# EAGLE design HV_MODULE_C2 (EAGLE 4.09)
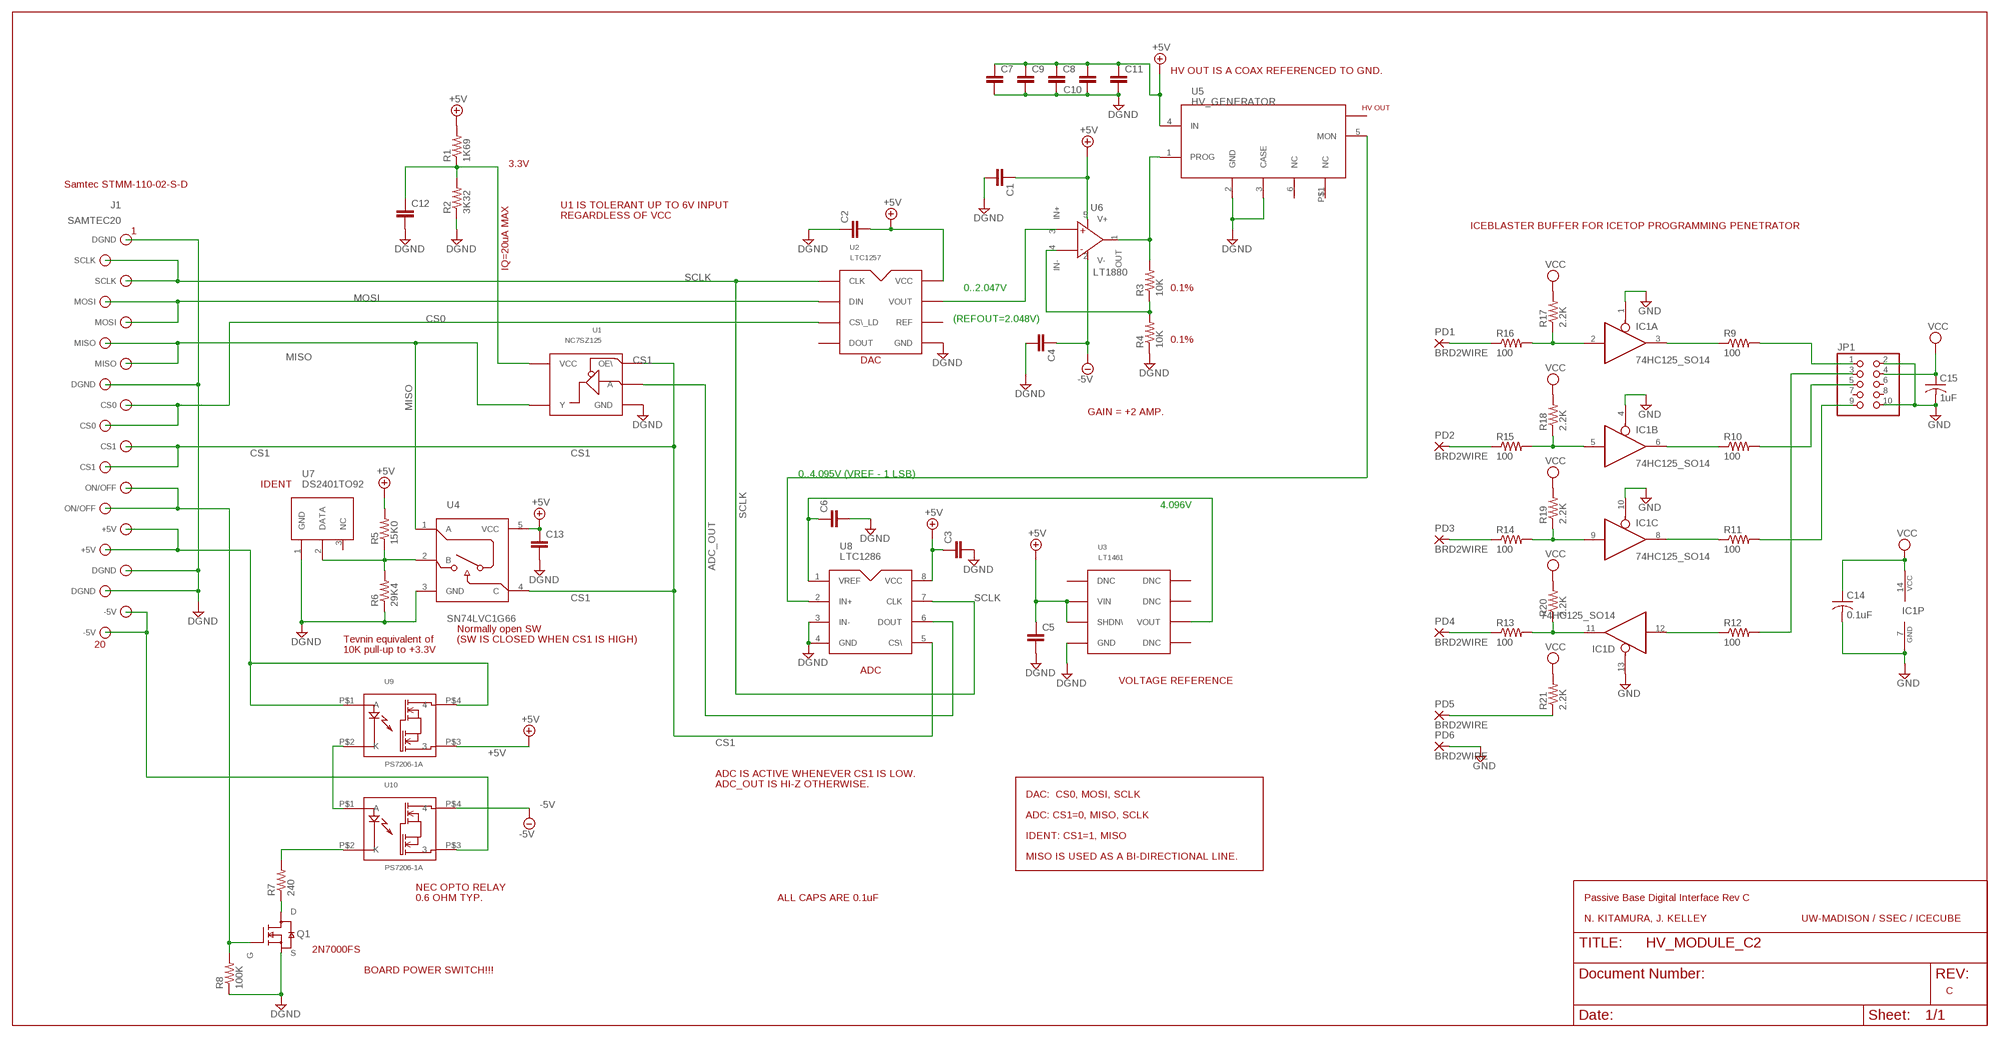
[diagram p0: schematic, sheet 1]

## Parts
C1  C-EUC0805  [C0805@1]
C2  C-EUC0805  [C0805@1]
C3  C-EUC0805  [C0805@1]
C4  C-EUC0805  [C0805@1]
C5  C-EUC0805  [C0805@1]
C6  C-EUC0805  [C0805@1]
C7  C-EUC0805  [C0805@1]
C8  C-EUC0805  [C0805@1]
C9  C-EUC0805  [C0805@1]
C10  C-EUC0805  [C0805@1]
C11  C-EUC0805  [C0805@1]
C12  C-EUC0805  [C0805@1]
C13  C-EUC0805  [C0805@1]
C14  0.1uF  C-USC0805  [C0805]
C15  1uF  C-USC0805  [C0805]
IC1  74HC125_SO14  [SO14]
J1  SAMTEC20  [SAMTEC20]
JP1  PINHD-2X5  [2X05]
PD1  BRD2WIRE  [BRD2WIRE]
PD2  BRD2WIRE  [BRD2WIRE]
PD3  BRD2WIRE  [BRD2WIRE]
PD4  BRD2WIRE  [BRD2WIRE]
PD5  BRD2WIRE  [BRD2WIRE]
PD6  BRD2WIRE  [BRD2WIRE]
Q1  2N7000FS  [TO92]
R1  1K69  R-US_M0805  [M0805]
R2  3K32  R-US_M0805  [M0805]
R3  10K  R-US_R0805  [R0805]
R4  10K  R-US_R0805  [R0805]
R5  15K0  R-US_M0805  [M0805]
R6  29K4  R-US_M0805  [M0805]
R7  240  R-US_M0805  [M0805]
R8  100K  R-US_M0805  [M0805]
R9  100  R-US_R0805  [R0805]
R10  100  R-US_R0805  [R0805]
R11  100  R-US_R0805  [R0805]
R12  100  R-US_R0805  [R0805]
R13  100  R-US_R0805  [R0805]
R14  100  R-US_R0805  [R0805]
R15  100  R-US_R0805  [R0805]
R16  100  R-US_R0805  [R0805]
R17  2.2K  R-US_R0805  [R0805]
R18  2.2K  R-US_R0805  [R0805]
R19  2.2K  R-US_R0805  [R0805]
R20  2.2K  R-US_R0805  [R0805]
R21  2.2K  R-US_R0805  [R0805]
U1  NC7SZ125  [SOT23-5]
U2  LTC1257  LTC1451  [SO8]
U3  LT1461  [SO8]
U4  SN74LVC1G66  [SOT23-5]
U5  HV_GENERATOR  EMCO1  [EMCO1]
U6  LT1880  [SOT23-5]
U7  DS2401TO92  [TO92]
U8  LTC1286  [SO8]
U9  PS7206-1A  [PS7206]
U10  PS7206-1A  [PS7206]

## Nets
3.3V: C12.1 R1.1 R2.2 U1.5(VCC)
+5V: C1.1 C2.2 C3.1 C5.1 C7.1 C8.1 C9.1 C10.2 C11.1 C13.1 R1.2 R5.2 U2.8(VCC) U3.2(VIN) U3.3(SHDN\) U4.5(VCC) U5.4(IN) U6.5(V+) U8.8(VCC) U9.P$3
-5V: C4.1 U6.2(V-) U10.P$4
ADC_OUT: U1.2(A) U8.6(DOUT)
BOARD_ONOFF: J1.P$13(ON/OFF) J1.P$14(ON/OFF) Q1.2(G) R8.2
CS0: J1.P$9(CS0) J1.P$10(CS0) U2.3(CS\_LD)
CS1: J1.P$11(CS1) J1.P$12(CS1) U1.1(OE\) U4.4(C) U8.5(CS\)
DGND: C1.2 C2.1 C3.2 C4.2 C5.2 C6.2 C7.2 C8.2 C9.2 C10.1 C11.2 C12.2 C13.2 J1.P$1(DGND) J1.P$8(DGND) J1.P$17(DGND) J1.P$18(DGND) Q1.1(S) R2.1 R4.1 R6.1 R8.1 U1.3(GND) U2.5(GND) U3.4(GND) U4.3(GND) U5.2(GND) U5.3(CASE) U7.1(GND) U8.3(IN-) U8.4(GND)
GND: C14.2 C15.2 IC1.1(A:OE) IC1.4(B:OE) IC1.7(P:GND) IC1.10(C:OE) IC1.13(D:OE) JP1.2 JP1.10 PD6.2(P)
HV_MON: U5.5(MON) U8.2(IN+)
HV_PROG: R3.2 U5.1(PROG) U6.1(OUT)
MISO: J1.P$6(MISO) J1.P$7(MISO) U1.4(Y) U4.1(A)
MOSI: J1.P$4(MOSI) J1.P$5(MOSI) U2.2(DIN)
N$1: U9.P$2(K) U10.P$1(A)
N$2: R5.1 R6.2 U4.2(B) U7.2(DATA)
N$3: IC1.2(A:I) R16.2 R17.1
N$4: Q1.3(D) R7.1
N$5: R7.2 U10.P$2(K)
N$6: IC1.9(C:I) R14.2 R19.1
N$7: IC1.11(D:O) R13.2 R20.1
N$8: IC1.12(D:I) R12.1
N$9: IC1.8(C:O) R11.1
N$10: R3.1 R4.2 U6.4(IN-)
N$11: IC1.6(B:O) R10.1
N$12: J1.P$15(+5V) J1.P$16(+5V) U9.P$1(A) U9.P$4
N$13: IC1.3(A:O) R9.1
N$14: IC1.5(B:I) R15.2 R18.1
N$15: J1.P$19(-5V) J1.P$20(-5V) U10.P$3
N$16: PD5.2(P) R21.1
N$24: U2.7(VOUT) U6.3(IN+)
N$32: C6.1 U3.6(VOUT) U8.1(VREF)
SCLK: J1.P$2(SCLK) J1.P$3(SCLK) U2.1(CLK) U8.7(CLK)
TCK_IN: PD1.2(P) R16.1
TCK_OUT: JP1.1 R9.2
TDI_IN: PD3.2(P) R14.1
TDI_OUT: JP1.9 R11.2
TDO_IN: JP1.3 R12.2
TDO_OUT: PD4.2(P) R13.1
TMS_IN: PD2.2(P) R15.1
TMS_OUT: JP1.5 R10.2
VCC: C14.1 C15.1 IC1.14(P:VCC) JP1.4 R17.2 R18.2 R19.2 R20.2 R21.2
Unconnected: JP1.6 JP1.7 JP1.8 U2.4(DOUT) U2.6(REF) U3.1(DNC) U3.5(DNC) U3.7(DNC) U3.8(DNC) U5.6(NC) U5.P$1(NC) U7.3(NC)

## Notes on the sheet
- HV OUT IS A COAX REFERENCED TO GND.
- 3.3V
- Samtec STMM-110-02-S-D
- U1 IS TOLERANT UP TO 6V INPUT
- REGARDLESS OF VCC
- ICEBLASTER BUFFER FOR ICETOP PROGRAMMING PENETRATOR
- IQ=20uA MAX
- 0..2.047V | 0.1%
- (REFOUT=2.048V)
- 0.1%
- DAC
- GAIN = +2 AMP.
- 0..4.095V (VREF - 1 LSB)
- IDENT
- 4.096V
- Normally open SW
- Tevnin equivalent of | (SW IS CLOSED WHEN CS1 IS HIGH)
- 10K pull-up to +3.3V
- ADC
- VOLTAGE REFERENCE
- ADC IS ACTIVE WHENEVER CS1 IS LOW.
- ADC_OUT IS HI-Z OTHERWISE.
- DAC:  CS0, MOSI, SCLK
- ADC: CS1=0, MISO, SCLK
- IDENT: CS1=1, MISO
- MISO IS USED AS A BI-DIRECTIONAL LINE.
- NEC OPTO RELAY
- 0.6 OHM TYP. | ALL CAPS ARE 0.1uF | Passive Base Digital Interface Rev C
- N. KITAMURA, J. KELLEY | UW-MADISON / SSEC / ICECUBE
- 2N7000FS
- BOARD POWER SWITCH!!!
- C

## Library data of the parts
C1-C13 = rcl:C-EU: CAPACITOR, European symbol
C14 C15 = rcl:C-US: CAPACITOR, American symbol
IC1 = JK1:74HC125_SO14
J1 = EMCO:SAMTEC20
JP1 = pinhead:PINHD-2X5: PIN HEADER
PD1-PD6 = JK1:BRD2WIRE: Board to wire, 0.076"
Q1 = FBD_lib:2N7000FS
R1-R21 = rcl:R-US_: RESISTOR, American symbol
U1 = HVM:NC7SZ125
U2 = EMCO:LTC1451: LINEAR TECHYNOLOGY 12-BIT DAC VOUT(MAX) = 4.095V, REFOUT (INTERNAL) = 2.048V
U3 = EMCO:LT1461: VOLTAGE REFERENCE. SUFFIX SPECIFIES VOLTAGE OUT.
U4 = HVM:SN74LVC1G66: BILATERAL ANALOG SWITCH NORMALLY OPEN
U5 = HVM:EMCO1: EMCO 9730 HV GENERATOR
U6 = HVM:LT1880: RAIL-TO-RAIL PICOAMP INPUT CURRENT PRECISION OPAMP
U7 = HVM:DS2401: DALLAS SILICON SERIAL NUMBER DEVICE
U8 = EMCO:LTC1286: 12-BIT ADC DIFF INPUT
U9 U10 = HVM:PS7206-1A

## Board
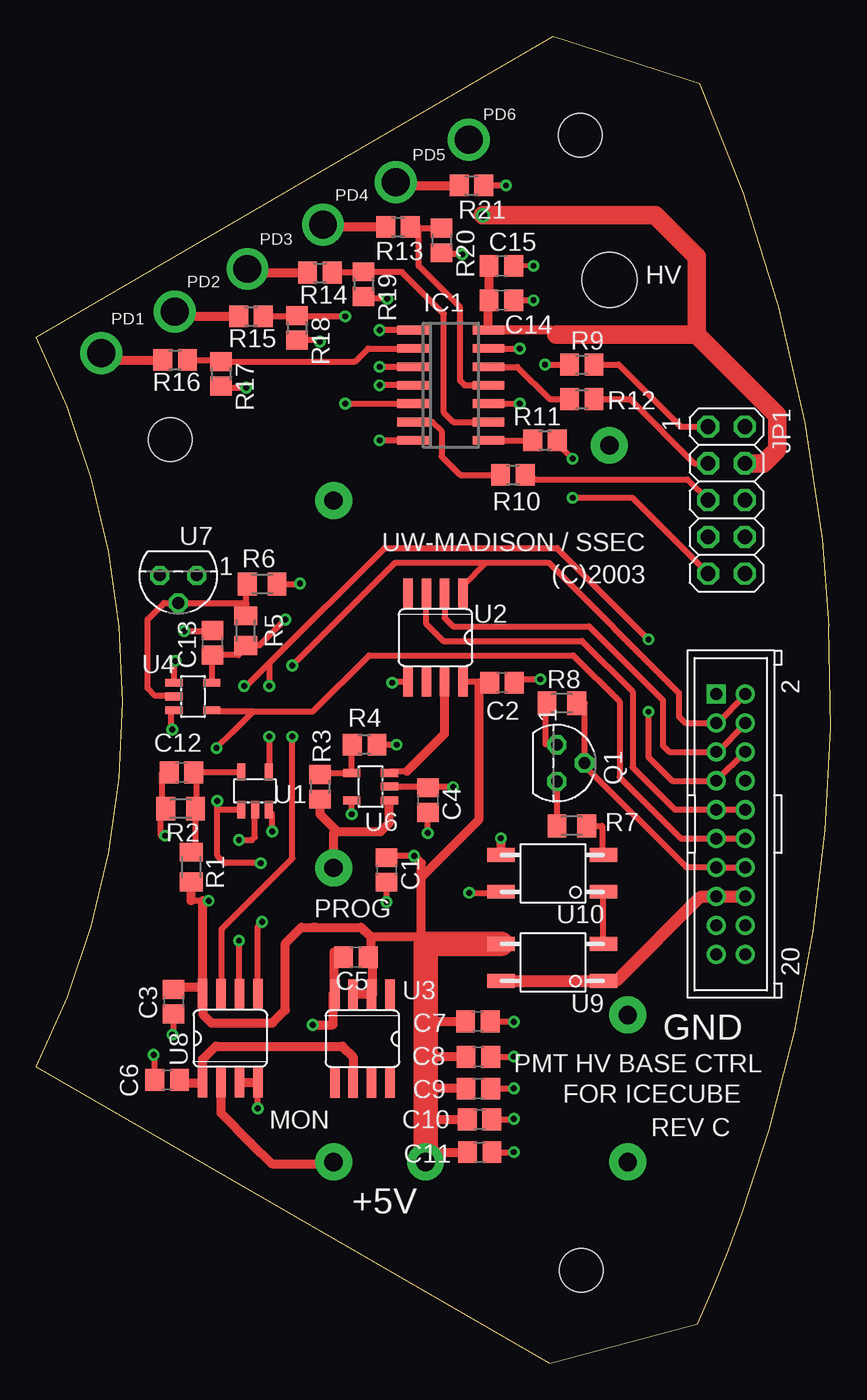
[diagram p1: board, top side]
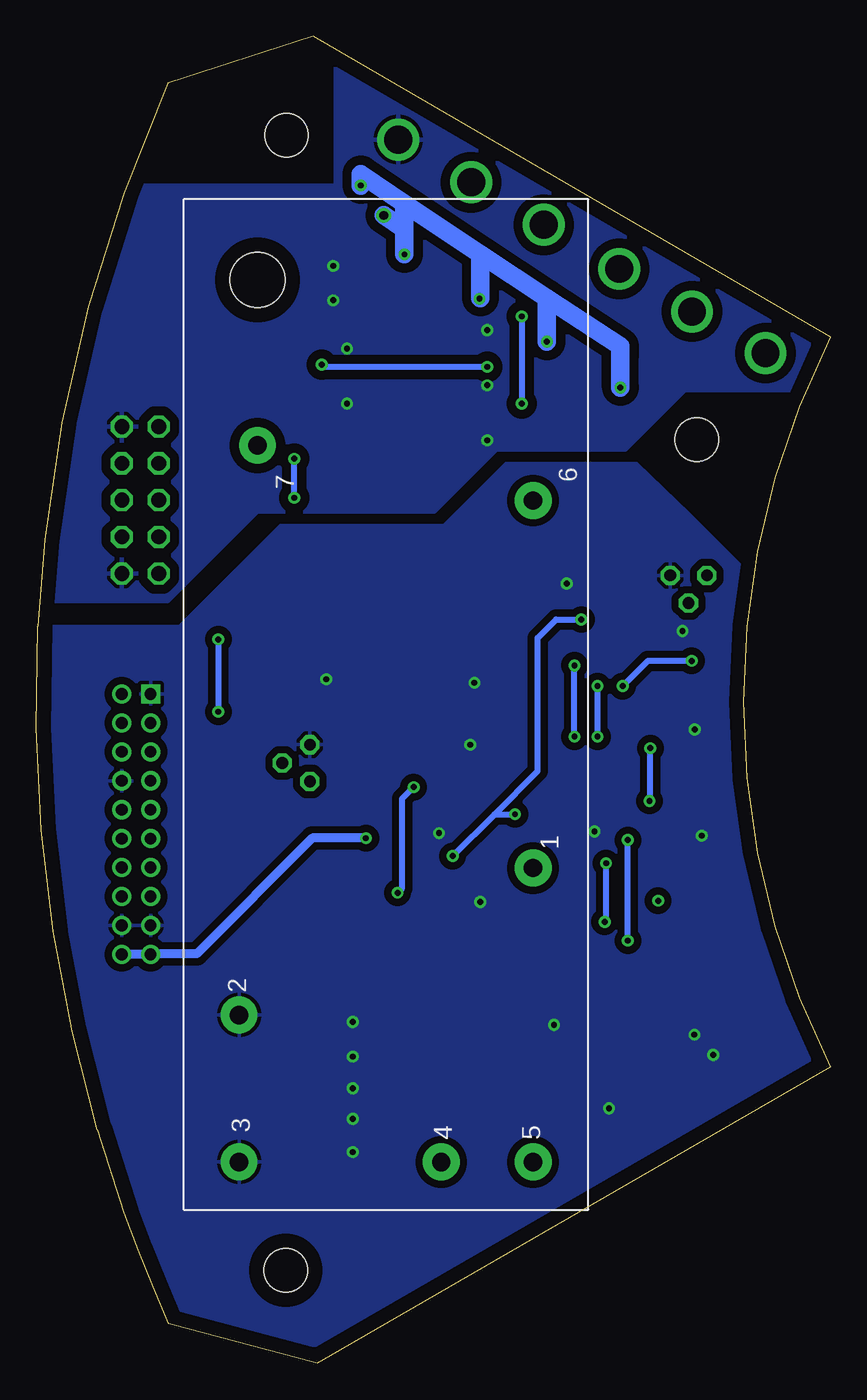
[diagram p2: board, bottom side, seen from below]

Size 54.9 x 91.74 mm. Coordinates in mm from the lower left corner, seen from the top.
Outline: 45.72,2.75 35.47,0 0,20.48 arc53 0,70.93 35.75,91.75 45.81,88.48 arc-18 54.31,56.93 54.78,50.95 arc-19 50.66,16.12
Outline: 45.72,2.75 arc5 48.81,10.42 50.66,16.12
Copper layers used: Top, Bottom
Holes 3 mm at 37.6,84.9 9.25,63.84 37.66,6.43
Milling: 10 lines

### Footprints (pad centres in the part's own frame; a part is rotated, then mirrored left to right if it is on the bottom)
C0805 = smd 1.3 x 1.5: 1 -0.85,0; 2 0.85,0
SO14 = smd 0.6 x 2.2: 1 -3.81,-2.6; 2 -2.54,-2.6; 3 -1.27,-2.6; 4 0,-2.6; 5 1.27,-2.6; 6 2.54,-2.6; 7 3.81,-2.6; 8 3.81,2.6; 9 2.54,2.6; 10 1.27,2.6; 11 0,2.6; 12 -1.27,2.6; 13 -2.54,2.6; 14 -3.81,2.6
SAMTEC20 = drill 0.813 square: P$1 -9,-1 | drill 0.813 round: P$2 -9,1; P$3 -7,-1; P$4 -7,1; P$5 -5,-1; P$6 -5,1; P$7 -3,-1; P$8 -3,1; P$9 -1,-1; P$10 -1,1; P$11 1,-1; P$12 1,1; P$13 3,-1; P$14 3,1; P$15 5,-1; P$16 5,1; P$17 7,-1; P$18 7,1; P$19 9,-1; P$20 9,1
2X05 = drill 1.016 octagon: 1 -5.08,-1.27; 2 -5.08,1.27; 3 -2.54,-1.27; 4 -2.54,1.27; 5 0,-1.27; 6 0,1.27; 7 2.54,-1.27; 8 2.54,1.27; 9 5.08,-1.27; 10 5.08,1.27
BRD2WIRE = drill 1.93 pad 2.54 round: 2 0,0
TO92 = drill 0.813 octagon: 1 -1.27,0; 2 0,1.905; 3 1.27,0
M0805 = smd 1.3 x 1.6: 1 -1.029,0; 2 1.029,0
R0805 = smd 1.3 x 1.5: 1 -0.85,0; 2 0.85,0
SOT23-5 = smd 0.55 x 1.2: 1 -0.95,-1.3; 2 0,-1.3; 3 0.95,-1.3; 4 0.95,1.3; 5 -0.95,1.3
SO8 = smd 0.66 x 2.032: 1 -1.905,-3.073; 2 -0.635,-3.073; 3 0.635,-3.073; 4 1.905,-3.073; 5 1.905,3.073; 6 0.635,3.073; 7 -0.635,3.073; 8 -1.905,3.073
EMCO1 = drill 1.27 pad 2.54 round: 1 37.338,24.13; 2 47.498,3.81; 3 57.658,3.81; 4 57.658,17.78; 5 57.658,24.13; 6 11.938,24.13; P$1 8.128,5.08 | hole 3.81: -3.302,5.08
TO92' = drill 0.813 octagon: 1 0,0; 2 1.27,1.905; 3 2.54,0
PS7206 = smd 1.93 x 0.965: P$1 -3.54,1.27; P$2 -3.54,-1.27; P$3 3.54,-1.27; P$4 3.54,1.27

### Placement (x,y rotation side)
C1  [C0805]  24.22,34.11 270 top
C2  [C0805]  32.19,47.06 180 top
C3  [C0805]  9.49,25.01 270 top
C4  [C0805]  27.07,38.94 270 top
C5  [C0805]  22.09,28.08 180 top
C6  [C0805]  9.05,19.59 180 top
C7  [C0805]  30.52,23.64 0 top
C8  [C0805]  30.55,21.18 0 top
C9  [C0805]  30.55,18.99 0 top
C10  [C0805]  30.64,16.87 180 top
C11  [C0805]  30.65,14.59 0 top
C12  [C0805]  10.04,40.84 180 top
C13  [C0805]  12.18,49.81 90 top
C14  32.15,73.49 0 top
C15  32.15,75.87 0 top
IC1  28.65,67.61 270 top
J1  47.99,37.27 270 top
JP1  47.7,59.67 270 top
PD1  4.5,69.83 0 top
PD2  9.58,72.72 0 top
PD3  14.6,75.66 0 top
PD4  19.82,78.7 0 top
PD5  24.84,81.64 0 top
PD6  29.88,84.6 0 top
Q1  35.98,41.49 270 top
R1  10.72,34.31 270 top
R2  9.98,38.34 0 top
R3  19.62,39.85 270 top
R4  22.7,42.77 180 top
R5  14.49,50.65 270 top
R6  15.62,53.88 180 top
R7  37.02,37.15 0 top
R8  36.32,45.63 0 top
R9  37.7,69.04 0 top
R10  32.94,61.42 0 top
R11  35.16,63.8 0 top
R12  37.7,66.66 0 top
R13  25,78.57 0 top
R14  19.6,75.39 0 top
R15  14.84,72.37 0 top
R16  9.6,69.36 0 top
R17  12.78,68.41 270 top
R18  18.02,71.58 270 top
R19  22.62,74.6 270 top
R20  28.02,77.61 270 top
R21  30.08,81.42 0 top
U1  15.12,39.58 0 top
U2  27.59,50.18 180 top
U3  22.54,22.43 180 top
U4  10.84,46.1 270 top
U5  44.69,71.58 270 bottom
U6  23.11,39.87 90 top
U7  DS2401TO92  [TO92']  11.09,54.47 180 top
U8  13.41,22.47 0 top
U9  35.66,27.71 180 top
U10  35.66,33.87 180 top

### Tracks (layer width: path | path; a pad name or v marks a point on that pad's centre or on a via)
3.3V
  Top 0.406: 11.01,40.84 11.01,40.78 | 11.01,40.84 C12.1 11.11,40.84 11.11,38.34 R2.2 11.01,35.34 R1.1 | U1.5 11.01,40.88 11.01,40.84
+5V  (via drill 0.41)
  Top 0.254: 26.93,28.98 26.71,28.98 26.71,29 | C13.1 12.18,49 12.14,49.04 12.13,49.03 | 14.52,49.51 14.49,49.55 R5.2
  Top 0.305: 22.91,28.1 C5.1 | 23.21,28.38 23.19,28.38 23.11,28.3 | 26.91,21.18 26.91,22.04 26.91,22.05
  Top 0.406: v21.81,37.96 U6.5 | C2.2 31.32,47.06 31.31,47.05 31.26,47.1 U2.8 | 26.91,19 26.92,18.99 26.91,18.99 26.91,16.87 | 26.93,21.18 26.91,21.18 | 26.91,21.18 C8.1 | 26.91,21.18 26.91,23.64 | 27.01,21.18 27.01,19 29.61,19 29.61,18.99 C9.1 | 11.51,31.98 10.71,31.98 | 24.22,34.92 24.21,34.91 | 24.22,34.92 C1.1 | v26.11,35.07 24.37,35.07 24.22,34.92 | 12.13,49.03 U4.5 | C13.1 13.97,48.96 14.52,49.51 | R5.2 15.43,49.62 v17.22,51.42
  Top 0.61: 23.21,25.51 23.21,25.4 | 23.21,25.51 U3.2 U3.3 | 23.21,28.38 23.21,25.51 | U3.3 | U3.3 21.91,25.6 | U2.8 29.5,47.43 | 22.91,28.1 23.11,28.3 23.11,29.5 | 26.61,33.6 30.61,37.6 30.61,47.05 31.31,47.05 | 26.61,33.6 26.61,29 26.71,29 26.81,29.1 26.41,29.5 23.11,29.5 | C9.1 26.92,18.99 | 26.91,16.87 C10.2 | 26.91,23.64 C7.1 | C8.1 27.01,21.18 | R1.2 10.71,31.98 | 11.51,25.53 U8.8 | 11.51,26.02 11.51,25.53 | v11.91,31.98 11.51,31.98 11.51,26.02 | U8.8 11.51,25.53 | 11.51,26.02 U8.8 | 11.51,25.53 11.51,24.13 12.11,23.53 16.32,23.53 17.22,24.43 17.22,29.04 18.33,30.15 19.29,30.15 | 23.11,29.5 23.1,29.5 22.46,30.15 19.29,30.15 | 19.29,30.15 19.13,30.15 | 9.45,26.02 9.49,25.97 C3.1 | 9.45,26.02 11.51,26.02 | 9.45,26.02 9.44,26.02 | 26.61,33.6 26.61,34.57 v26.11,35.07 | U5.4 26.91,13.8 27.71,14.59 C11.1
  Top 1.676: U9.P$3 26.93,28.98 26.93,21.18 | 26.91,22.05 26.91,13.8
  Bottom 0.406: v21.81,37.96 23.22,37.96 23.26,37.93 | v26.11,35.07 23.26,37.93 | v17.22,51.42 18.97,51.42 20.24,50.15 20.24,40.94 23.26,37.93
-5V  (via drill 0.41)
  Top 0.254: 24.41,39.86 U6.2
  Top 0.406: 24.41,39.86 27.04,39.86 27.07,39.82 C4.1 27.07,39.83 v28.81,39.83 | U10.P$4 32.12,32.55 32.15,32.53 v29.92,32.53
  Bottom 0.406: v28.81,39.83 29.6,39.04 29.6,32.85 v29.92,32.53
ADC_OUT  (via drill 0.41)
  Top 0.254: 14.05,29.22 v14.01,29.22 | U1.2 15.12,38.29 U1.2
  Top 0.406: U8.6 14.05,29.22 | v14.01,36.18 14.91,36.18 15.11,36.38 U1.2
  Bottom 0.254: 14.02,29.22 14.05,29.19 | v14.01,29.22 14.02,29.22 | 14.02,29.22 14.01,29.23
  Bottom 0.406: 14.01,29.23 v14.01,36.18
BOARD_ONOFF
  Top 0.254: Q1.2 37.89,41.33 | 47.01,34.3 J1.P$13 | J1.P$14 49.01,34.3 | J1.P$14 | J1.P$14
  Top 0.406: 37.91,41.49 37.91,41.4 | Q1.2 37.91,41.49 | R8.2 37.91,45.63 37.91,41.49 | 37.89,41.33 44.91,34.3 47.01,34.3 | J1.P$13 J1.P$14
CS0
  Top 0.254: J1.P$10 49.01,38.3 | J1.P$10 | J1.P$10
  Top 0.406: U2.3 26.96,51.1 28.11,49.95 37.71,49.95 41.21,46.45 41.21,41.2 44.14,38.27 J1.P$9 J1.P$10
CS1  (via drill 0.41)
  Top 0.254: U8.5 15.31,25.43 | 48.99,36.22 49.01,36.2 | 48.99,36.22 J1.P$12 | 48.94,36.27 48.99,36.22 | 12.09,45.21 12.13,45.17 U4.4 12.13,45.08 12.14,45.07
  Top 0.406: U8.5 15.31,30.22 v15.61,30.52 | 12.51,38.28 U1.1 | 12.51,38.28 12.51,35.08 13.01,34.58 v15.51,34.58 | 12.51,38.28 v12.51,38.88 | 48.94,36.27 J1.P$11 44.54,36.27 40.31,40.5 40.31,45.75 37.11,48.95 23.01,48.95 19.13,45.07 15,45.07 | v12.46,42.53 13.57,43.64 15,45.07 | 15,45.07 12.14,45.07
  Bottom 0.254: v12.51,38.88 12.62,38.88 12.46,39.04 | 15.61,30.49 15.63,30.46 | v15.61,30.52 15.61,30.49 | 15.61,30.49 15.51,30.59
  Bottom 0.406: 12.46,39.04 v12.46,42.53 | 15.51,30.59 v15.51,34.58
DGND  (via drill 0.41)
  Top 0.254: 16.01,38.28 U1.3 | v18.23,53.9 18.25,53.88 18.33,53.8 | 12.14,50.63 C13.2
  Top 0.305: C5.2 21.21,28.1 21.21,28.3
  Top 0.406: U2.5 24.67,47.1 v24.61,47.05 | R4.1 v24.9,42.77 v24.91,42.76 | v9.41,22.73 9.51,22.73 9.49,22.75 C3.2 | v15.31,17.63 15.31,19.33 | C7.2 32.98,23.64 v33.01,23.6 | v33.01,21.2 33.01,21.1 32.93,21.18 C8.2 | v33.01,19 33.11,19 33.1,18.99 C9.2 | v33.01,16.9 33.11,16.9 33.08,16.87 C10.1 | C11.2 v33,14.59 v33.01,14.6 | R8.1 35.21,45.63 35.21,42.8 35.91,42.8 35.91,42.76 | 35.91,42.76 35.91,42.7 | Q1.1 35.91,42.76 | v16.31,36.78 16.31,37.98 16.01,38.28 | 8.71,38.34 8.71,38.28 | 8.71,38.34 R2.1 8.61,38.34 8.61,36.48 v8.91,36.48 | C12.2 8.71,40.84 8.71,38.34 | v9.4,43.81 9.3,43.81 9.3,45.15 U4.3 | R6.1 18.25,53.88 | v8.11,21.33 v8.11,21.32 8.2,21.23 C6.2 | C1.2 v24.22,31.9 v24.21,31.89 | C4.2 27.07,36.66 v27.07,36.66 | C2.1 33.04,47.08 33.26,47.29 v34.84,47.29 | v10.24,50.63 12.14,50.63
  Top 0.61: 20.59,28.43 20.61,28.4 21.21,28.4 21.24,28.38 21.29,28.38 21.21,28.3 20.61,28.3 20.61,25.6 20.64,25.58 U3.4 20.52,25.51 20.51,25.5 20.51,23.4 v19.11,23.4 | U8.4 15.32,19.33 15.31,19.33 15.24,19.4 U8.3
  pour Bottom (isolate 0.508): -3.26,45.7 9.76,58.72 13.41,62.21 22.46,62.21 26.75,57.93 38.02,57.93 45,50.94 57.07,50.94 57.23,50.78 57.23,-1.13 -3.26,-1.13
GND  (via drill 0.41)
  Top 0.305: v33.41,70.15 33.57,70.15 | C15.2 v34.37,75.87
  Top 0.406: IC1.1 v23.73,71.42 | IC1.4 v23.73,67.61 | IC1.7 v23.73,63.8 | IC1.10 v33.41,66.34 | IC1.13 v33.41,70.15 | C14.2 v34.37,73.49
  pour Bottom (isolate 0.635): 57.23,52.69 45.8,52.69 39.61,58.88 27.38,58.88 23.1,63.17 14.21,63.17 10.08,67.29 -3.73,67.29 -8.02,71.58 -8.02,93.01 -6.75,94.28 34.21,94.28 34.21,81.42 53.74,81.42 57.23,77.93
HV_MON
  Top 0.61: U8.2 12.78,17.29 14.84,15.22 | 14.84,15.22 | 14.84,15.22 16.27,13.8 20.56,13.8 U5.5
HV_PROG
  Top 0.406: 24.41,37.36 24.31,37.26 | 24.41,38.66 U6.1
  Top 0.61: R3.2 19.62,37.95 20.81,36.76 | 20.81,36.76 23.81,36.76 24.41,37.36 24.41,38.66 | 20.81,36.76 20.77,36.76 20.72,36.81 20.56,36.66 U5.1
MISO  (via drill 0.41)
  Top 0.254: 16.07,40.92 16.01,40.98 | 16.07,40.92 U1.4 | 16.07,40.92 16.07,40.94 16.11,40.98 16.11,40.94 | J1.P$6 | J1.P$7 | 9.54,48.49 v9.6,48.56 | v14.37,46.82 14.52,46.82 | 16.11,48.4
  Top 0.406: J1.P$7 43.94,40.27 42.31,41.9 v42.31,45.05 | J1.P$7 J1.P$6 | v42.31,50.05 35.99,56.37 24.08,56.37 16.11,48.4 | v16.11,43.32 16.11,40.94 | 16.11,48.4 v16.11,46.82 | U4.1 9.54,48.49 | 14.52,46.82 16.11,48.4
  Bottom 0.254: v42.31,50.05 42.31,50 42.3,49.99 42.31,49.98
  Bottom 0.406: v16.11,46.82 v16.11,43.32 | v9.6,48.56 12.62,48.56 v14.37,46.82 | 42.31,49.98 v42.31,45.05
MOSI
  Top 0.254: 49.01,44.2 48.99,44.22 J1.P$4 | J1.P$5 47.08,42.27
  Top 0.406: J1.P$5 43.74,42.27 43.31,42.7 43.31,45.85 38.21,50.95 28.81,50.95 28.23,51.53 U2.2 | 47.08,42.27 49.01,44.2
N$1
  Top 0.406: 39.23,28.98 39.31,28.9 | U9.P$2 39.23,28.98 | U10.P$1 39.2,29.01 39.23,28.98
N$2
  Top 0.254: 14.53,53.9 14.59,53.9 R6.2 14.59,53.8 14.53,53.8 14.52,53.8 | 14.52,51.66 14.52,51.68 R5.1
  Top 0.406: 14.52,51.68 14.52,53.8 | U4.2 9.54,46.11 9.6,46.18 8.17,46.18 7.7,46.66 7.7,51.42 8.84,52.57 U7.2 14.49,52.57 14.52,52.53 14.52,51.74 14.49,51.7 R5.1
N$3
  Top 0.305: 12.78,69.36 R17.1
  Top 0.406: R16.2 12.78,69.36 | R17.1 22.04,69.26 22.94,70.15 IC1.2
N$4
  Top 0.406: 36.01,37.15 36.01,37.1 | R7.1 36.01,37.15 | Q1.3 36.01,40.22 36.01,37.15
N$5
  Top 0.406: 39.11,35.14 39.11,35.1 | 39.11,35.14 U10.P$2 | R7.2 39.11,37.15 39.11,35.14
N$6
  Top 0.305: R19.1 22.62,75.55 22.46,75.39 | IC1.9 31.35,65.07
  Top 0.406: 22.46,75.39 R14.2 | R19.1 25.26,75.45 28.18,72.53 28.18,65.71 28.81,65.07 IC1.9
N$7
  Top 0.305: R13.2 25.85,78.62 25.95,78.72 26.22,78.46 26.33,78.46 26.43,78.57
  Top 0.406: 26.22,78.46 R20.1 | IC1.11 29.6,67.61 29.29,67.93 29.29,73.01 26.43,75.87 26.43,78.57
N$8
  Top 0.305: 36.75,66.66 R12.1
  Top 0.406: IC1.12 33.26,68.88 35.48,66.66 36.75,66.66
N$9
  Top 0.305: R11.1 34.37,63.8
  Top 0.406: IC1.8 R11.1
N$10
  Top 0.406: R4.2 21.82,42.77 21.81,42.76 U6.4 19.77,40.82 19.65,40.7 R3.1
N$11
  Top 0.305: 31.99,61.42 | 31.99,61.42 R10.1
  Top 0.406: IC1.6 27.38,65.07 28.02,64.44 28.02,62.69 29.29,61.42 31.99,61.42
N$12
  Top 0.813: J1.P$16 J1.P$15 | J1.P$15 46.94,32.27 46.91,32.3 | J1.P$15 45.94,32.27 40.1,26.44 U9.P$1 32.27,26.44 32.21,26.5 32.15,26.44 U9.P$4
N$13  (via drill 0.41)
  Top 0.305: 36.59,69.04 R9.1
  Top 0.406: IC1.3 v23.73,68.88 | v35.16,69.04 36.59,69.04
  Bottom 0.305: 35,68.88 v35.16,69.04
  Bottom 0.406: v23.73,68.88 35,68.88
N$14  (via drill 0.41)
  Top 0.305: 18.02,72.37 | 18.02,72.37 R18.1 | v21.35,72.37
  Top 0.406: R15.2 18.02,72.37 v21.35,72.37 | v21.35,66.34 IC1.5
  Bottom 0.406: v21.35,72.37 v21.35,66.34
N$15  (via drill 0.41)
  Top 0.61: U10.P$3 v32.12,36.29 v32.11,36.3
  Bottom 0.61: v32.11,36.3 35.81,36.3 43.81,28.3 47.01,28.3 J1.P$19 J1.P$20 | J1.P$20 49.01,28.3 | J1.P$20
N$16
  Top 0.61: PD5.2 24.84,81.58 25,81.42 R21.1
N$24
  Top 0.254: 24.31,40.76 24.37,40.82 U6.3
  Top 0.406: 24.37,40.86 24.37,40.82 24.37,40.78 24.53,40.94 25.64,40.94
  Top 0.61: U2.7 28.23,43.53 25.64,40.94
N$32
  Top 0.61: C6.1 9.95,19.59 10.14,19.4 U8.1 11.51,21.02 12.41,21.93 21.16,21.93 21.91,21.18 U3.6 21.91,19.31 21.91,19.3
SCLK  (via drill 0.41)
  Top 0.254: 12.81,25.43 12.78,25.46 U8.7 12.79,25.55 12.81,25.53 | 29.5,53.73 U2.1 | 49.01,46.2 48.99,46.22 J1.P$2 | J1.P$3 47.08,44.27 | v17.7,48.24
  Top 0.406: J1.P$3 44.84,44.27 44.41,44.7 44.41,46.35 35.41,55.35 31.11,55.35 | 31.11,55.35 29.5,53.73 | 47.08,44.27 49.01,46.2 | 12.81,25.53 12.81,30.02 17.7,34.91 v17.7,43.32 | 31.11,55.35 24.8,55.35 v17.7,48.24
  Bottom 0.406: v17.7,43.32 v17.7,48.24
TCK_IN
  Top 0.61: PD1.2 4.5,69.7 4.84,69.36 R16.1
TCK_OUT
  Top 0.406: JP1.1 44.53,64.75 40.24,69.04 R9.2
TDI_IN
  Top 0.61: 14.58,75.66 14.52,75.71 | PD3.2 14.58,75.66 | R14.1 14.84,75.39 14.58,75.66
TDI_OUT  (via drill 0.41)
  Top 0.305: 36.01,63.59 R11.2
  Top 0.406: v37.07,62.53 36.01,63.59 | v37.07,59.83 41.19,59.83 JP1.9
  Bottom 0.406: v37.07,59.83 v37.07,62.53
TDO_IN
  Top 0.305: 38.49,66.66 38.5,66.66 R12.2
  Top 0.406: JP1.3 45.48,62.21 41.04,66.66 38.49,66.66
TDO_OUT
  Top 0.61: 19.79,78.7 19.76,78.72 | PD4.2 19.79,78.7 | R13.1 19.92,78.57 19.79,78.7
TMS_IN
  Top 0.61: PD2.2 9.47,72.72 9.44,72.69 9.76,72.37 R15.1
TMS_OUT
  Top 0.305: R10.2 34.21,61.42 34.53,61.1
  Top 0.406: 34.53,61.1 45,61.1 JP1.5
VCC  (via drill 0.41, 0.61)
  Top 0.305: v19.6,70.63 19.5,70.73 | 28.02,76.66 R20.2 | R17.2 12.78,67.45 | R19.2 22.62,73.64 22.68,73.59 22.72,73.59 22.78,73.64 22.83,73.59 | 31.03,81.42 | 31.03,81.42 R21.2
  Top 0.406: 19.5,70.73 R18.2 | v29.45,76.66 28.02,76.66 | 12.78,67.45 v14.52,67.45 | v24.26,73.59 22.83,73.59 | v32.46,81.42 31.03,81.42
  Top 0.61: 31.35,75.87 | 31.35,75.87 C15.1 31.19,75.87 | 31.35,75.87 31.3,75.81 C14.1 31.19,73.49 31.25,73.43 IC1.14 35.64,71.42 35.96,71.1
  Top 1.27: JP1.4 50.24,62.21 51.19,63.17 51.19,65.55 45.64,71.1 | 45.64,71.1 35.96,71.1 | v30.88,79.36 42.78,79.36 45.64,76.5 45.64,71.26 | 45.64,71.26 45.64,71.1 | 45.64,71.26
  Bottom 0.305: 19.6,73.64 19.6,73.96 | 24.21,73.64 v24.26,73.59 | v24.26,73.59 | 19.6,73.64 | v14.52,67.45
  Bottom 1.27: v14.52,67.45 14.52,69.68 14.52,70.31 19.6,73.64 | 19.6,73.64 v19.6,70.63 | 19.6,73.64 24.21,76.66 | 24.21,76.66 29.45,80.15 | 29.45,80.15 29.45,78.41 | 29.45,78.41 v29.45,76.66 | 29.45,80.15 32.46,82.22 v32.46,81.42 | 24.21,76.66 24.21,73.64 | 29.45,78.41 v30.88,79.36

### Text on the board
tNames: HV | 1 | UW-MADISON / SSEC | (C)2003 | PROG | GND | PMT HV BASE CTRL | FOR ICECUBE | MON | REV C | +5V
